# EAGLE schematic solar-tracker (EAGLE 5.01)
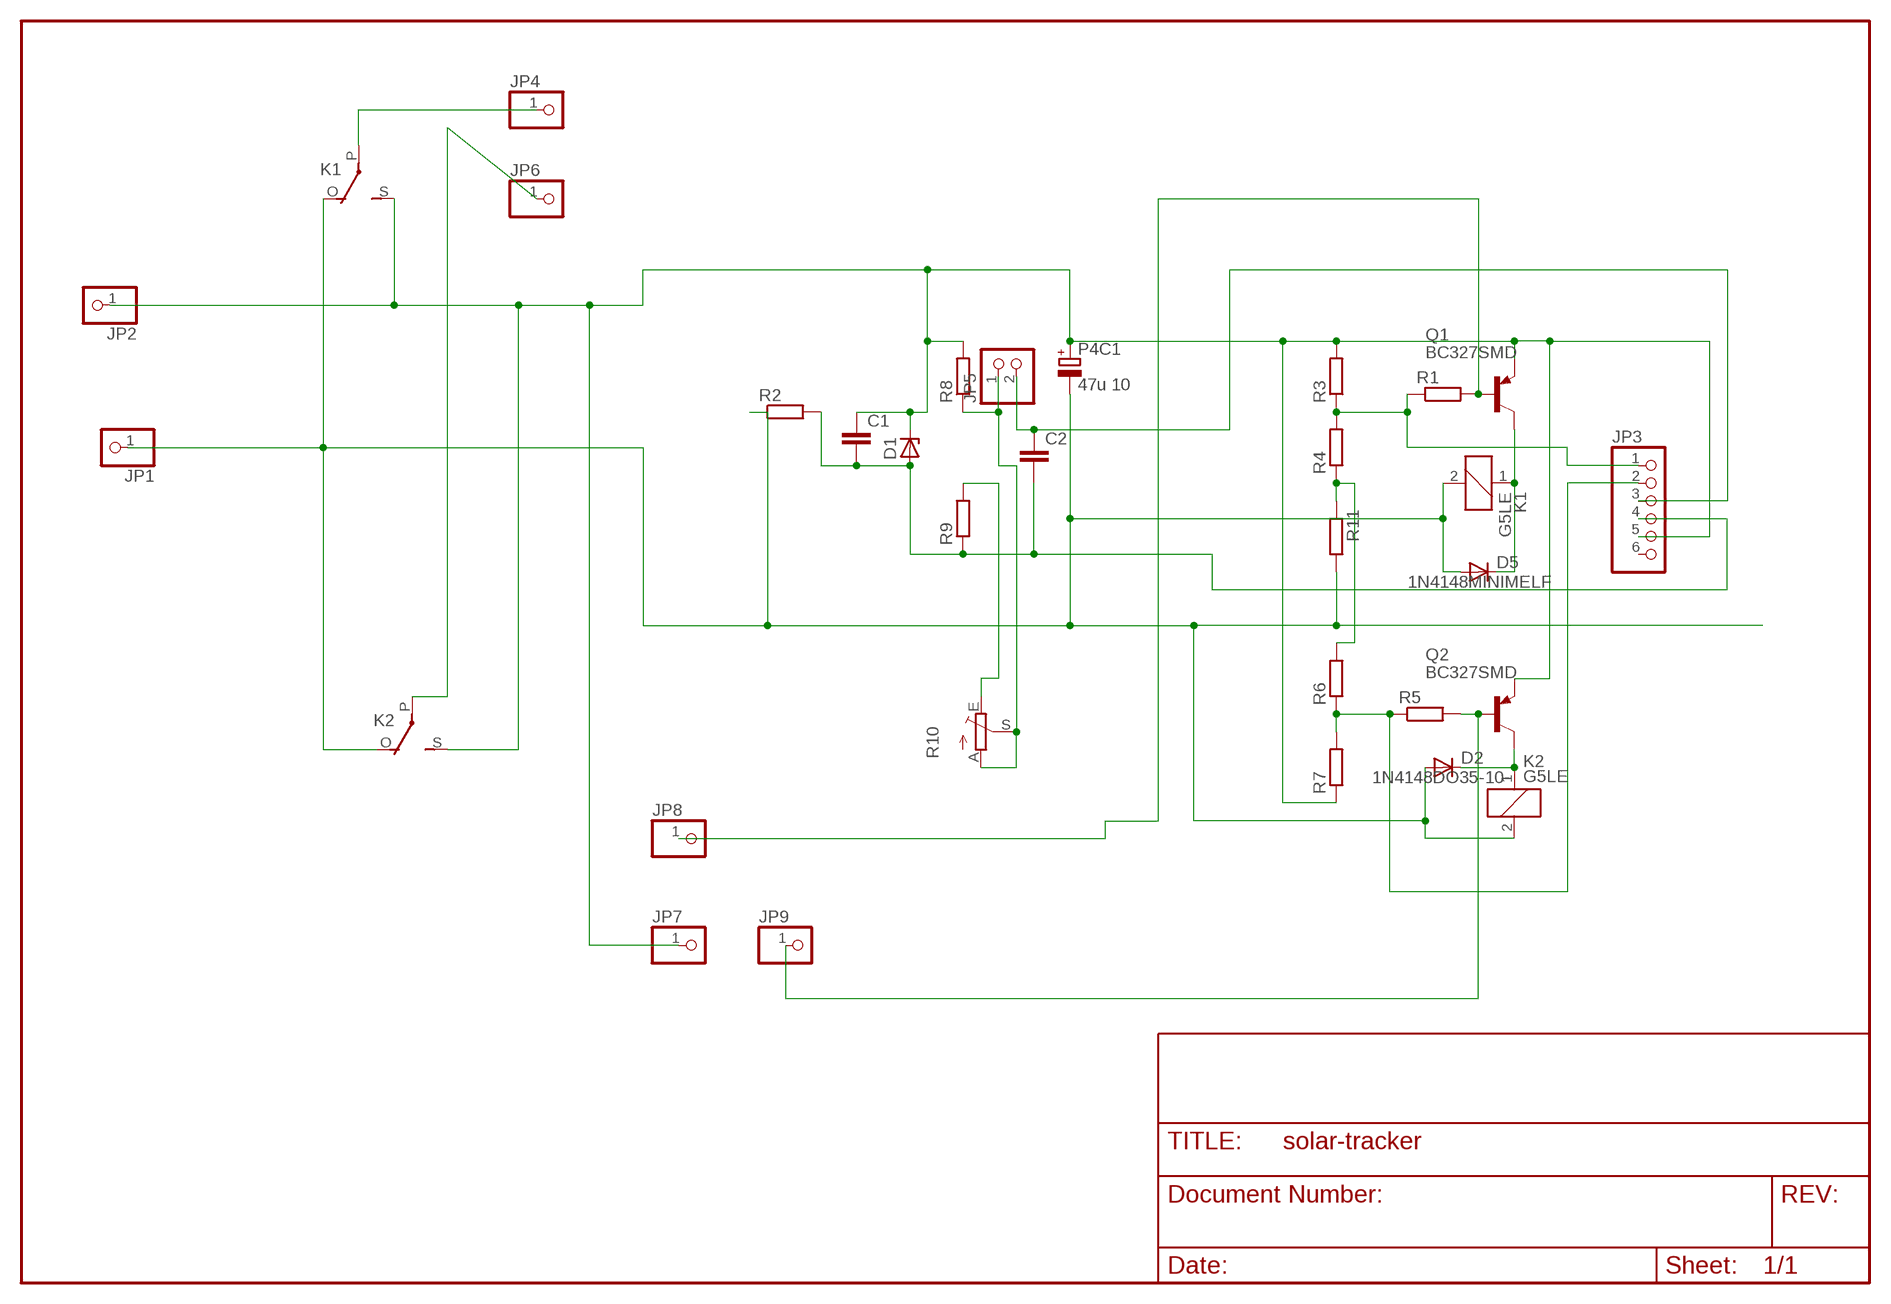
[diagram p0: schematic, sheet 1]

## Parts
C1  C-EUC1206  [C1206]
C2  C-EUC1206  [C1206]
D1  ZENER-DIODESOT23  [SOT23]
D2  1N4148DO35-10  [DO35-10]
D5  1N4148MINIMELF  [MINIMELF]
JP1  PINHD-1X1  [1X01]
JP2  PINHD-1X1  [1X01]
JP3  PINHD-1X6  [1X06]
JP4  PINHD-1X1  [1X01]
JP5  PINHD-1X2  [1X02]
JP6  PINHD-1X1  [1X01]
JP7  PINHD-1X1  [1X01]
JP8  PINHD-1X1  [1X01]
JP9  PINHD-1X1  [1X01]
K1  G5LE  [G5LE]
K2  G5LE  [G5LE]
P4C1  47u 10  CPOL-EUE5-8.5  [E5-8,5]
Q1  BC327SMD  [SOT23-BEC]
Q2  BC327SMD  [SOT23-BEC]
R1  R-EU_R0805  [R0805]
R2  R-EU_M1206  [M1206]
R3  R-EU_R0805  [R0805]
R4  R-EU_R2010  [R2010]
R5  R-EU_R0805  [R0805]
R6  R-EU_R2010  [R2010]
R7  R-EU_R0805  [R0805]
R8  R-EU_R0805  [R0805]
R9  R-EU_R0805  [R0805]
R10  TRIM_EU-CA6V  [CA6V]
R11  R-EU_R0805  [R0805]

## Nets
N$1: R9.2 R10.E
N$2: JP4.1 K1.P(2:P)
N$3: JP5.1 R8.1 R10.A R10.S
N$4: JP6.1 K2.P(2:P)
N$5: C1.2 C2.2 D1.1(A) JP3.4 R2.2 R9.1
N$6: R4.1 R6.2 R11.1
N$7: C2.1 JP3.3 JP5.2
N$8: JP8.1 Q1.B R1.2
N$10: JP3.1 R1.1 R3.1 R4.2
N$11: D5.C K1.1 Q1.C
N$12: D2.C K2.1 Q2.C
N$13: JP3.2 R5.1 R6.1 R7.2
N$15: JP9.1 Q2.B R5.2
V+: C1.1 D1.3(C) JP2.1 JP3.5 JP7.1 K1.S(2:S) K2.S(2:S) P4C1.+ Q1.E Q2.E R3.2 R7.1 R8.2
V-: D2.A D5.A JP1.1 K1.2 K1.O(2:O) K2.2 K2.O(2:O) P4C1.- R2.1 R11.2
Unconnected: JP3.6

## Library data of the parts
C1 C2 = rcl-2:C-EU: CAPACITOR, European symbol
D1 = diode-1:ZENER-DIODE: Z-Diode
D2 D5 = diode-1:1N4148: DIODE
JP1 JP2 JP4 JP6-JP9 = pinhead(2):PINHD-1X1: PIN HEADER
JP3 = pinhead:PINHD-1X6: PIN HEADER
JP5 = pinhead:PINHD-1X2: PIN HEADER
K1 K2 = relay:G5LE: RELAY 1 x switch, 10 A/120 V AC, 8 A/30 V DC, Omron
P4C1 = rcl:CPOL-EU: POLARIZED CAPACITOR, European symbol
Q1 Q2 = transistor-pnp:BC327*: PNP Transistror
R1-R9 R11 = rcl-2:R-EU_: RESISTOR, European symbol
R10 = pot:TRIM_EU-: POTENTIOMETER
